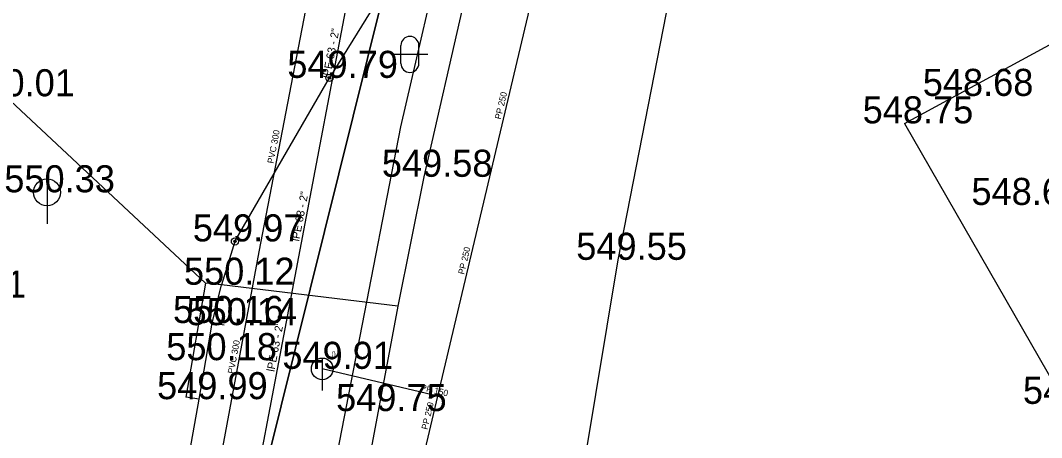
# Model space of a CAD drawing. Extents: x -669995 to -669686, y -1125551 to -1125263.
# Drawn here: x -669860.35 to -669832.03, y -1125420.77 to -1125409.22 of the extents above; entities that cross this region are included whole.
import ezdxf

# ---------------------------------------------------------------- set-up
doc = ezdxf.new("R2010")
doc.units = 0
for name, color, linetype in [('G_Bod_tecka', 7, 'Continuous'), ('G_Bod_vyska', 7, 'Continuous'), ('G_Cesty_Schody', 7, 'Continuous'), ('G_Plochy_zpevnene', 7, 'Continuous'), ('G_Ploty', 7, 'Continuous'), ('G_Ploty_vstupy', 7, 'Continuous'), ('G_Site-kanalizace', 7, 'Continuous'), ('G_Site-Sloupy', 7, 'Continuous'), ('G_Z_ELsilove_nadz_kotovane', 7, 'Continuous'), ('G_Z_ELsilove_podz_kotovane', 7, 'Continuous'), ('G_Z_KANAL_podz_kotovane', 7, 'Continuous'), ('G_Z_KANAL_podz_priblizne', 7, 'Continuous'), ('G_Z_PLYNY_podz_geodeticky', 7, 'Continuous'), ('G_Z_VODA_podz_kotovane', 7, 'Continuous'), ('G_Zelen-okraj', 7, 'Continuous'), ('G_Zelen-Znacky', 7, 'Continuous'), ('Vrstva 11', 7, 'Continuous'), ('Vrstva 17', 7, 'Continuous'), ('Vrstva 2', 7, 'Continuous'), ('Vrstva 26', 7, 'Continuous'), ('Vrstva 3', 7, 'Continuous'), ('Vrstva 4', 7, 'Continuous'), ('Vrstva 5', 7, 'Continuous'), ('Vrstva 8', 7, 'Continuous')]:
    doc.layers.add(name, color=color, linetype=linetype)

msp = doc.modelspace()

# ---------------------------------------------------------------- linework, layer by layer
at = {"layer": 'G_Bod_tecka'}
for p, q in [((-669851.78, -1125410.81), (-669851.78, -1125410.81)), ((-669834.15, -1125411.31), (-669834.15, -1125411.31)), ((-669835.83, -1125412.07), (-669835.83, -1125412.07)), ((-669849.16, -1125413.55), (-669849.16, -1125413.55)), ((-669859.61, -1125413.98), (-669859.61, -1125413.98)), ((-669832.8, -1125414.33), (-669832.8, -1125414.33)), ((-669854.4, -1125415.34), (-669854.4, -1125415.34)), ((-669843.77, -1125415.85), (-669843.77, -1125415.85)), ((-669854.77, -1125416.54), (-669854.77, -1125416.54)), ((-669855.06, -1125417.6), (-669855.06, -1125417.6)), ((-669854.7, -1125417.66), (-669854.7, -1125417.66)), ((-669855.26, -1125418.63), (-669855.26, -1125418.63)), ((-669851.98, -1125418.87), (-669851.98, -1125418.87)), ((-669855.39, -1125419.71), (-669855.39, -1125419.71)), ((-669850.43, -1125420.04), (-669850.43, -1125420.04))]:
    msp.add_line(p, q, dxfattribs=at)
at = {"layer": 'G_Cesty_Schody'}
msp.add_line((-669835.83, -1125412.07), (-669831.37, -1125419.84), dxfattribs=at)
at = {"layer": 'G_Plochy_zpevnene'}
for p, q in [((-669843.77, -1125415.85), (-669841.82, -1125405.89)), ((-669847.54, -1125406.46), (-669849.16, -1125413.55)), ((-669849.16, -1125413.55), (-669849.88, -1125417.13)), ((-669845.47, -1125426.05), (-669843.77, -1125415.85)), ((-669854.7, -1125417.66), (-669855.03, -1125417.6)), ((-669850.43, -1125420.04), (-669851.75, -1125427.17))]:
    msp.add_line(p, q, dxfattribs=at)
for points in [[(-669849.88, -1125417.13), (-669854.77, -1125416.54)], [(-669849.88, -1125417.13), (-669850.43, -1125420.04)]]:
    msp.add_lwpolyline(points, dxfattribs=at)
at = {"layer": 'G_Ploty'}
for p, q in [((-669860.76, -1125411.32), (-669855.22, -1125416.5)), ((-669855.22, -1125416.5), (-669855.76, -1125419.65)), ((-669854.77, -1125416.54), (-669855.22, -1125416.5)), ((-669855.03, -1125417.6), (-669854.77, -1125416.54)), ((-669855.21, -1125418.64), (-669855.03, -1125417.6)), ((-669855.39, -1125419.71), (-669855.21, -1125418.64)), ((-669855.39, -1125419.71), (-669855.76, -1125419.65))]:
    msp.add_line(p, q, dxfattribs=at)
for points in [[(-669850.65, -1125408.99), (-669851.78, -1125410.81)], [(-669854.4, -1125415.34), (-669854.77, -1125416.54)]]:
    msp.add_lwpolyline(points, dxfattribs=at)
at = {"layer": 'G_Ploty_vstupy'}
msp.add_line((-669855.94, -1125422.74), (-669855.39, -1125419.71), dxfattribs=at)
msp.add_lwpolyline([(-669854.4, -1125415.34), (-669851.78, -1125410.81)], dxfattribs=at)
at = {"layer": 'G_Site-kanalizace'}
for p, q in [((-669859.61, -1125413.605), (-669859.61, -1125414.855)), ((-669851.98, -1125418.57), (-669851.98, -1125419.47))]:
    msp.add_line(p, q, dxfattribs=at)
for centre, radius in [((-669859.61, -1125413.98), 0.375), ((-669851.98, -1125418.87), 0.3)]:
    msp.add_circle(centre, radius, dxfattribs=at)
at = {"layer": 'G_Site-Sloupy'}
for centre, radius in [((-669851.78, -1125410.81), 0.1), ((-669851.78, -1125410.81), 0.0348), ((-669854.4, -1125415.34), 0.1), ((-669854.4, -1125415.34), 0.0348)]:
    msp.add_circle(centre, radius, dxfattribs=at)
at = {"layer": 'G_Z_ELsilove_nadz_kotovane'}
msp.add_lwpolyline([(-669860.28, -1125448.68), (-669849.93, -1125407.07)], dxfattribs=at)
at = {"layer": 'G_Z_ELsilove_podz_kotovane'}
msp.add_lwpolyline([(-669793.678, -1125277.309), (-669806.73, -1125294.49), (-669822.69, -1125326.67), (-669837.43, -1125364.93), (-669849.93, -1125407.07), (-669860.28, -1125448.68)], dxfattribs=at)
at = {"layer": 'G_Z_KANAL_podz_kotovane'}
msp.add_line((-669848.77, -1125419.63), (-669851.98, -1125418.87), dxfattribs=at)
for points in [[(-669854.06, -1125441.98), (-669853.75, -1125440.68), (-669848.77, -1125419.63), (-669845.09, -1125404.08), (-669844.67, -1125402.32)], [(-669848.77, -1125419.63), (-669851.98, -1125418.87)]]:
    msp.add_lwpolyline(points, dxfattribs=at)
at = {"layer": 'G_Z_KANAL_podz_priblizne'}
msp.add_lwpolyline([(-669859.5, -1125451.55), (-669856.48, -1125430.45), (-669853.73, -1125415.63), (-669852.14, -1125407.38), (-669851.85, -1125406.81), (-669846.78, -1125392.66), (-669840.64, -1125375.45), (-669843.45, -1125370.23)], dxfattribs=at)
at = {"layer": 'G_Z_PLYNY_podz_geodeticky'}
msp.add_lwpolyline([(-669839.68, -1125381.34), (-669843.56, -1125391.5), (-669845.77, -1125398.22), (-669846.85, -1125401.64), (-669847.2, -1125402.75), (-669848.28, -1125405.76), (-669848.45, -1125406.31), (-669848.51, -1125406.54), (-669849.81, -1125412.17), (-669852.19, -1125424.43), (-669853.31, -1125431.05), (-669856.64, -1125450), (-669860.14, -1125455.63), (-669860.74, -1125456.58)], dxfattribs=at)
at = {"layer": 'G_Z_VODA_podz_kotovane'}
msp.add_lwpolyline([(-669858.63, -1125450.57), (-669858.25, -1125448.42), (-669857.85, -1125445.05), (-669856.38, -1125434.43), (-669854.37, -1125424.91), (-669851.09, -1125407.69), (-669849.25, -1125402.21), (-669840.03, -1125375.63), (-669840.08, -1125374.27), (-669839.76, -1125372.61), (-669839.5, -1125370.59), (-669837.98, -1125365.03), (-669838.35, -1125363.15), (-669838.04, -1125362.68), (-669836.94, -1125362.97)], dxfattribs=at)
at = {"layer": 'G_Zelen-okraj'}
msp.add_line((-669835.83, -1125412.07), (-669823.54, -1125405.41), dxfattribs=at)
at = {"layer": 'G_Zelen-Znacky'}
for p, q in [((-669849.8, -1125410.41), (-669849.8, -1125409.91)), ((-669849.3, -1125410.41), (-669849.3, -1125409.91)), ((-669849.05, -1125410.16), (-669850.05, -1125410.16))]:
    msp.add_line(p, q, dxfattribs=at)
for centre, start, end in [((-669849.55, -1125409.911), 0, 180), ((-669849.55, -1125410.411), 180, 0)]:
    msp.add_arc(centre, 0.25, start, end, dxfattribs=at)
at = {"layer": 'Vrstva 11'}
msp.add_line((-669848.77, -1125419.63), (-669851.98, -1125418.87), dxfattribs=at)
for points in [[(-669854.06, -1125441.98), (-669853.75, -1125440.68), (-669848.77, -1125419.63), (-669845.09, -1125404.08), (-669844.67, -1125402.32)], [(-669848.77, -1125419.63), (-669851.98, -1125418.87)]]:
    msp.add_lwpolyline(points, dxfattribs=at)
at = {"layer": 'Vrstva 17'}
msp.add_lwpolyline([(-669859.5, -1125451.55), (-669856.48, -1125430.45), (-669853.73, -1125415.63), (-669852.14, -1125407.38), (-669851.85, -1125406.81), (-669846.78, -1125392.66), (-669840.64, -1125375.45), (-669843.45, -1125370.23)], dxfattribs=at)
at = {"layer": 'Vrstva 26'}
msp.add_lwpolyline([(-669858.63, -1125450.57), (-669858.245, -1125448.421), (-669857.85, -1125445.05), (-669856.38, -1125434.43), (-669854.37, -1125424.91), (-669851.09, -1125407.69), (-669849.25, -1125402.21), (-669840.03, -1125375.63), (-669840.08, -1125374.27), (-669839.76, -1125372.61), (-669839.5, -1125370.59), (-669837.98, -1125365.03), (-669838.35, -1125363.15), (-669838.04, -1125362.68), (-669836.94, -1125362.97)], dxfattribs=at)
at = {"layer": 'Vrstva 5'}
msp.add_line((-669849.93, -1125407.07), (-669860.28, -1125448.68), dxfattribs=at)
at = {"layer": 'Vrstva 8'}
msp.add_line((-669851.98, -1125418.87), (-669851.98, -1125418.87), dxfattribs=at)

# ---------------------------------------------------------------- texts
at = {"layer": 'G_Bod_vyska'}
for s, p in [('549.79', (-669852.948, -1125410.81)), ('550.01', (-669861.906, -1125411.32)), ('548.68', (-669835.328, -1125411.31)), ('548.75', (-669836.994, -1125412.07)), ('549.58', (-669850.326, -1125413.55)), ('550.33', (-669860.796, -1125413.98)), ('548.68', (-669833.978, -1125414.33)), ('549.97', (-669855.568, -1125415.34)), ('549.55', (-669844.936, -1125415.85)), ('550.12', (-669855.814, -1125416.54)), ('550.31', (-669863.254, -1125416.9)), ('550.16', (-669856.118, -1125417.6)), ('550.14', (-669855.744, -1125417.66)), ('550.18', (-669856.304, -1125418.63)), ('549.91', (-669853.086, -1125418.87)), ('549.99', (-669856.56, -1125419.71)), ('548.96', (-669832.55, -1125419.84)), ('549.75', (-669851.596, -1125420.04))]:
    msp.add_text(s, height=0.75, dxfattribs=at).set_placement(p)
at = {"layer": 'Vrstva 2'}
msp.add_text('\xa0()', height=0.1316, dxfattribs=at).set_placement((-669851.775, -1125418.518))
at = {"layer": 'Vrstva 3'}
for s, rotation, p in [('PP 250', 76.7124, (-669847.027, -1125411.971)), ('PVC 300', 79.117, (-669853.332, -1125413.193)), ('PP 250', 76.6934, (-669848.044, -1125416.267)), ('PVC 300', 79.5036, (-669854.431, -1125419.016)), ('PP 150', 346.6934, (-669849.26, -1125419.46)), ('PP 250', 76.7029, (-669849.062, -1125420.565))]:
    msp.add_text(s, height=0.1755, rotation=rotation, dxfattribs=at).set_placement(p)
at = {"layer": 'Vrstva 4'}
for p in [(-669851.761, -1125410.834), (-669852.62, -1125415.349), (-669853.308, -1125418.962)]:
    msp.add_text('lPE 63 - 2"', height=0.21938, rotation=79.2429, dxfattribs=at).set_placement(p)

doc.saveas('drawing.dxf')
